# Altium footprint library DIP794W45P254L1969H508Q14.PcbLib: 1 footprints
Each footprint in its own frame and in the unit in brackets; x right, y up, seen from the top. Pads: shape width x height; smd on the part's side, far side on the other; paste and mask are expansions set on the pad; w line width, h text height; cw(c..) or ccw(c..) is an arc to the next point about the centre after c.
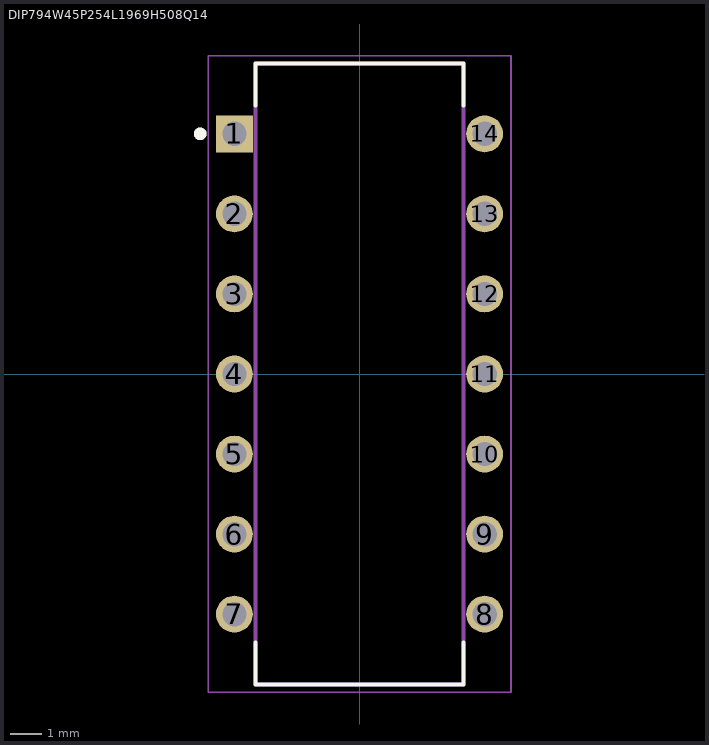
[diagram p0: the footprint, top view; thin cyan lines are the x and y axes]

## DIP794W45P254L1969H508Q14 [mm]
pads (14):
  rect 1.17x1.17 / inner round 1.17 / far side rect 1.17x1.17 hole 0.77 mask+0.102: 1(-3.97,7.62)
  round 1.17 hole 0.77 mask+0.102: 2(-3.97,5.08) 3(-3.97,2.54) 4(-3.97,0) 5(-3.97,-2.54) 6(-3.97,-5.08) 7(-3.97,-7.62) 8(3.97,-7.62) 9(3.97,-5.08) 10(3.97,-2.54) 11(3.97,0) 12(3.97,2.54) 13(3.97,5.08) 14(3.97,7.62)
Top Overlay:
  circle w0.2: c-5.055,7.62 r0.1
  lines w0.127: -3.3,-8.525 -3.3,-9.845 3.3,-9.845 3.3,-8.525 ; -3.3,8.525 -3.3,9.845 3.3,9.845 3.3,8.525
Assembly Top:
  circle w0.2: c-5.055,7.62 r0.1
  lines w0.127: -3.3,-9.845 3.3,-9.845 3.3,9.845 -3.3,9.845 -3.3,-9.845
Courtyard Top:
  lines w0.05: -4.805,-10.095 4.805,-10.095 4.805,10.095 -4.805,10.095 -4.805,-10.095
3D body "step_temp.STEP": height 5.08, standoff -3.18, extent -3.935,-9.653 3.935,9.653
